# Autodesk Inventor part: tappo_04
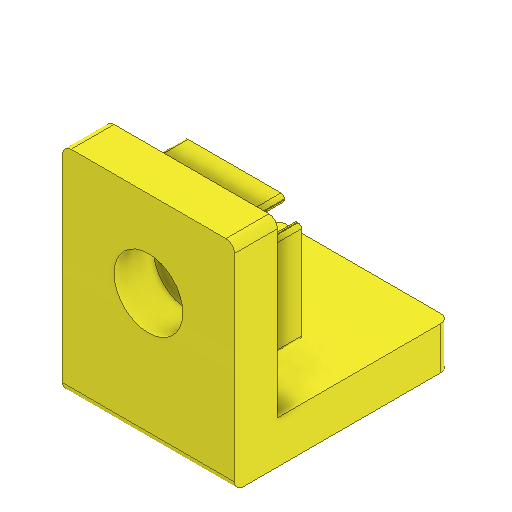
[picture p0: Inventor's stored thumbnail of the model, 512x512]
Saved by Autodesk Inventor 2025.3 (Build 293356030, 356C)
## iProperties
Created: 2026-02
Part Number: tappo_04
Material: Generico
Document SubType Name: Modeling
Designer: R5800u
Density: 1 g/cm^3
Appearance: Giallo canarino
Author: R5800u
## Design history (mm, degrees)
sketch "Schizzo1"
  geometry: L1 (10, 10)-(-10, 10); L2 (-10, 10)-(-10, -10); L3 (-10, -10)-(10, -10); L4 (10, -10)-(10, 10); L5 (10, 10)-(-10, -10); L6 (-10, 10)-(10, -10); L7 (6, -8)-(3, -8) reference; L8 (6, -7.061)-(6, -8) reference; L9 (2.939, -4)-(6, -7.061) reference; L10 (0, 0)-(0, -10); L11 (2.939, -4)-(0, -4); L12 (3, -8)-(0, -8); L13 (0, -7.8)-(3, -7.8); L14 (3, -7.8)-(5.8, -7.8); L15 (5.8, -7.8)-(5.8, -7.144); L16 (5.8, -7.144)-(2.856, -4.2); L17 (2.856, -4.2)-(0, -4.2); L18 (0, -7.8)-(-3, -7.8); L19 (-3, -7.8)-(-5.8, -7.8); L20 (-5.8, -7.8)-(-5.8, -7.144); L21 (-5.8, -7.144)-(-2.856, -4.2); L22 (-2.856, -4.2)-(0, -4.2)
  constraints: 38 end point, 4 symmetric about line, 3 midpoint, 3 perpendicular, 2 parallel, 2 point on line, 1 horizontal, 4 other
  dimensions: "d0" = 20 distance of L3.end L2.end; "d1" = 20 distance of L2.end L1.end; "d2" = 0.2 distance between parallel lines of L12 L13
  node "Riferimento1"
  node "Riferimento2"
  node "Riferimento3"
extrude "Estrusione1" new body sketch "Schizzo1" distance "d3" = 5; taper "d4" = 0 deg
extrude "Estrusione2" new body sketch "Schizzo1" distance "d5" = 1.9; taper "d6" = 0 deg; dims "d11" = 5, "d12" = 0
pattern_circular "Serie circolare1" dims angle "d8" = 360 deg
fillet "Raccordo2" dims "d13" = 0.4
sketch "Schizzo2"
  geometry: 1 further point
hole "Foro1" sketch "Schizzo2" at (0, 0) diameter "d14" = 4.3; stored, may be unused: countersink angle "d18" = 90 deg, drill point angle "d20" = 118 deg; dims "d15" = 6, "d16" = 8, "d17" = 4.6, "d19" = 8
fillet "Raccordo3" dims "d21" = 1
sketch "Schizzo3"
  geometry: L1 (0, 0)-(20, 0) reference; L2 (20, 0)-(20, 5) reference; L3 (0, 5)-(20, 5) reference; L4 (0, 0)-(0, 5) reference; 1 further point
extrude "Estrusione3" join sketch "Schizzo3" distance "d22" = 5; taper "d23" = 0 deg
sketch "Schizzo4"
  geometry: L1 (-10, -15)-(10, -15) reference; L2 (-10, 9)-(-10, -15) reference; L3 (10, -15)-(-10, -15); L4 (-10, -15)-(-10, -10.05); L5 (-10, -10.05)-(10, -10.05); L6 (10, -10.05)-(10, -15); 1 further point
  constraints: 8 end point, 2 parallel, 1 horizontal, 1 perpendicular, 1 point on line
  dimensions: "d24" = 4.95 distance of L3.end L4.end
extrude "Estrusione4" join sketch "Schizzo4" distance "d25" = 20; taper "d26" = 0 deg
fillet "Raccordo4" dims "d27" = 1
node "Solido1"
node "Solido2"
node "Linea chiusa proiettata1"
